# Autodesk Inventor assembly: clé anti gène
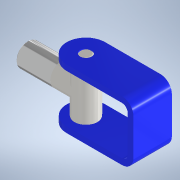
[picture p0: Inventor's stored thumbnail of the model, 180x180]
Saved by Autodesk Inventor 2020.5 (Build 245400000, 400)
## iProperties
Created: 2022-10
Part Number: clé anti gène
Document SubType Name: Assembly
Designer: mel
Author: mel
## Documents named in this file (4)
- D:\travail\année 2022-2023\I2D\procédés\clé anti gène.iam
- D:\travail\année 2022-2023\I2D\procédés\coque.ipt
- D:\travail\année 2022-2023\I2D\procédés\pivot.ipt
- D:\travail\année 2022-2023\I2D\procédés\axe.ipt
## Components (3 placed, 3 different names)
1. coque:1 — Logement:1, Angle:1
2. pivot:1 — Logement:1, Logement:2
3. axe:1 — Logement:2, Angle:1
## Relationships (3: Insert 2, Angle 1)
- Logement:1 [Insert]: coque:1 ↔ pivot:1
- Logement:2 [Insert]: pivot:1 ↔ axe:1
- Angle:1: coque:1 ↔ axe:1
